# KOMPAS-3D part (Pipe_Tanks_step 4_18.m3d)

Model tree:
1. X Axis
2. Y Axis
3. Z Axis  (labels: Valve Dy 50; Pipe Dn 20; Bend 90 Dn 20)
     Òîëùèíà ñòåíêè 1 = 1

Referenced files in C:\Documents and Settings\kashirsky\Мои документы\Camtasia Studio\Pipelines3D\Tanks\: Tanks_step 4.a3d
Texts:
  Pipe Dn 50
  Steel ASTM A295
  Three Point Plane
  Plane at Angle
  Line and Point Plane
  Axis through Two Vertices
  Axis of Feature
  Axis of Conical Surface
  Axis through Edge
  Trim by Surface
  Trim by Sketch
  Feature with No History
  Intersection Axis of Two Planes
  Two Line Plane
  Line and Face Plane
  Bend by line
  Hole in sheet body
  Cut in sheet body
  Point in CM
  Linear Dimension from Line to Point
  Surface Finish Symbol
  Geometric Tolerance Symbol
  Leader #1
  Leader #2
  Leader #3
  Shape Deviations and Datum
  Node point number
  Mark of coordination axis
  Node point designation
  Mark/Reference designation with leader
  Mark/reference designation on line
  Mark/Reference designation without leader
  Valve Dy 50
  Pipe Dn 20
  Bend 90 Dn 20
  Plane of section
